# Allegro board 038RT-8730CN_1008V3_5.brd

Outline 645.8 x 470 mm; copper layers: TOP, L02_DGND, L03_SIGNAL, L04_DGND, L05_SIGNAL, L06_DGND, L07_SIGNAL, L08_DGND, L09_SIGNAL, L10_DGND, L11_SIGNAL, L12_DGND, L13_DPS, L14_DGND, L15_DPS, L16_DGND, L17_DPS, L18_DGND, L19_DPS, L20_DGND, L21_DPS, L22_DGND, L23_USER_CBIT, L24_DPS, L25_DGND, L26_SIGNAL, L27_DGND, L28_SIGNAL, L29_DGND, L30_SIGNAL, L31_DGND, L32_SIGNAL, L33_DGND, L34_SIGNAL, L35_DGND, BOTTOM. Coordinates in mm from the lower left corner of the outline.
Outline path: 0,465 0,323.39 0,322.6 arc(1.46,319.06) 5,317.6 50.8,317.6 50.8,152.4 5,152.4 arc(1.47,150.94) 0,147.4 0,5.79 0,5 arc(1.46,1.46) 5,0 640.8,0 arc(644.34,1.46) 645.8,5 645.8,465 arc(644.34,468.54) 640.8,470 5,470 arc(1.46,468.54) 0,465

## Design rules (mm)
net group DIFFPAIR0: nets S0_HSDM S0_HSDP
net group DIFFPAIR2: nets S0_PB5 S0_PB6
net group DIFFPAIR3: nets S0_1_AOUT_RN S0_1_AOUT_RP
net group DIFFPAIR4: nets S0_PA20 S0_PA21
net group DIFFPAIR5: nets S0_2_AOUT_RN S0_2_AOUT_RP
net group DIFFPAIR6: nets S0_PA22 S0_PA23
net group DIFFPAIR7: nets S0_PB5_AOUT_RP_2 S0_PB6_AOUT_RN_2
net group DIFFPAIR8: nets S0_PB3 S0_PB4
net group DIFFPAIR9: nets S0_1_AOUT_LN S0_1_AOUT_LP
net group DIFFPAIR10: nets S0_2_AOUT_LN S0_2_AOUT_LP
net group DIFFPAIR11: nets S0_PB3_AOUT_LP_2 S0_PB4_AOUT_LN_2
net group DIFFPAIR12: nets S0_PA24 S0_PA25
net group DIFFPAIR13: nets S0_PA28 S0_PA29
net group DIFFPAIR14: nets S0_MIPITX_DATAN_0 S0_MIPITX_DATAP_0
net group DIFFPAIR15: nets S0_MIPITX_CKN S0_MIPITX_CKP
net group DIFFPAIR16: nets S0_MIPITX_DATAN_1 S0_MIPITX_DATAP_1
net group DIFFPAIR17: nets S1_HSDM S1_HSDP
net group DIFFPAIR19: nets S1_MIPITX_CKN S1_MIPITX_CKP
net group DIFFPAIR20: nets S1_MIPITX_DATAN_0 S1_MIPITX_DATAP_0
net group DIFFPAIR21: nets S1_MIPITX_DATAN_1 S1_MIPITX_DATAP_1
net group DIFFPAIR22: nets S1_PB3_AOUT_LP_2 S1_PB4_AOUT_LN_2
net group DIFFPAIR23: nets S1_PB5_AOUT_RP_2 S1_PB6_AOUT_RN_2
net group DIFFPAIR24: nets S1_PA22 S1_PA23
net group DIFFPAIR25: nets S1_PA28 S1_PA29
net group DIFFPAIR26: nets S1_2_AOUT_LN S1_2_AOUT_LP
net group DIFFPAIR27: nets S1_2_AOUT_RN S1_2_AOUT_RP
net group DIFFPAIR28: nets S1_PA20 S1_PA21
net group DIFFPAIR29: nets S1_PA24 S1_PA25
net group DIFFPAIR30: nets S1_1_AOUT_LN S1_1_AOUT_LP
net group DIFFPAIR31: nets S1_1_AOUT_RN S1_1_AOUT_RP
net group DIFFPAIR32: nets S1_PB5 S1_PB6
net group DIFFPAIR33: nets S1_PB3 S1_PB4
net group DIFFPAIR35: nets S2_HSDM S2_HSDP
net group DIFFPAIR36: nets S3_MIPITX_CKN S3_MIPITX_CKP
net group DIFFPAIR37: nets S3_MIPITX_DATAN_0 S3_MIPITX_DATAP_0
net group DIFFPAIR38: nets S3_MIPITX_DATAN_1 S3_MIPITX_DATAP_1
net group DIFFPAIR39: nets S3_PB5_AOUT_RP_2 S3_PB6_AOUT_RN_2
net group DIFFPAIR40: nets S3_PA22 S3_PA23
net group DIFFPAIR41: nets S3_PB3_AOUT_LP_2 S3_PB4_AOUT_LN_2
net group DIFFPAIR42: nets S3_PA28 S3_PA29
net group DIFFPAIR43: nets S3_2_AOUT_LN S3_2_AOUT_LP
net group DIFFPAIR44: nets S3_PA24 S3_PA25
net group DIFFPAIR45: nets S3_2_AOUT_RN S3_2_AOUT_RP
net group DIFFPAIR46: nets S3_PA20 S3_PA21
net group DIFFPAIR47: nets S3_1_AOUT_LN S3_1_AOUT_LP
net group DIFFPAIR48: nets S3_PB3 S3_PB4
net group DIFFPAIR49: nets S3_1_AOUT_RN S3_1_AOUT_RP
net group DIFFPAIR50: nets S3_PB5 S3_PB6
net group DIFFPAIR52: nets S3_HSDM S3_HSDP
net group DIFFPAIR53: nets S2_MIPITX_CKN S2_MIPITX_CKP
net group DIFFPAIR54: nets S2_MIPITX_DATAN_0 S2_MIPITX_DATAP_0
net group DIFFPAIR55: nets S2_MIPITX_DATAN_1 S2_MIPITX_DATAP_1
net group DIFFPAIR56: nets S2_PB3_AOUT_LP_2 S2_PB4_AOUT_LN_2
net group DIFFPAIR57: nets S2_PA28 S2_PA29
net group DIFFPAIR58: nets S2_PB5_AOUT_RP_2 S2_PB6_AOUT_RN_2
net group DIFFPAIR59: nets S2_PA22 S2_PA23
net group DIFFPAIR60: nets S2_2_AOUT_LN S2_2_AOUT_LP
net group DIFFPAIR61: nets S2_2_AOUT_RN S2_2_AOUT_RP
net group DIFFPAIR62: nets S2_PA20 S2_PA21
net group DIFFPAIR63: nets S2_PA24 S2_PA25
net group DIFFPAIR64: nets S2_1_AOUT_LN S2_1_AOUT_LP
net group DIFFPAIR65: nets S2_PB3 S2_PB4
net group DIFFPAIR66: nets S2_1_AOUT_RN S2_1_AOUT_RP
net group DIFFPAIR67: nets S2_PB5 S2_PB6
net group DIFFPAIR69: nets S7_HSDM S7_HSDP
net group DIFFPAIR70: nets S7_MIPITX_CKN S7_MIPITX_CKP
net group DIFFPAIR71: nets S7_MIPITX_DATAN_0 S7_MIPITX_DATAP_0
net group DIFFPAIR72: nets S7_MIPITX_DATAN_1 S7_MIPITX_DATAP_1
net group DIFFPAIR73: nets S7_PB3_AOUT_LP_2 S7_PB4_AOUT_LN_2
net group DIFFPAIR74: nets S7_PA28 S7_PA29
net group DIFFPAIR75: nets S7_PB5_AOUT_RP_2 S7_PB6_AOUT_RN_2
net group DIFFPAIR76: nets S7_PA22 S7_PA23
net group DIFFPAIR77: nets S7_2_AOUT_LN S7_2_AOUT_LP
net group DIFFPAIR78: nets S7_2_AOUT_RN S7_2_AOUT_RP
net group DIFFPAIR79: nets S7_PA24 S7_PA25
net group DIFFPAIR80: nets S7_PA20 S7_PA21
net group DIFFPAIR81: nets S7_1_AOUT_LN S7_1_AOUT_LP
net group DIFFPAIR82: nets S7_PB3 S7_PB4
net group DIFFPAIR83: nets S7_1_AOUT_RN S7_1_AOUT_RP
net group DIFFPAIR84: nets S7_PB5 S7_PB6
net group DIFFPAIR86: nets S6_HSDM S6_HSDP
net group DIFFPAIR87: nets S6_MIPITX_CKN S6_MIPITX_CKP
net group DIFFPAIR88: nets S6_MIPITX_DATAN_0 S6_MIPITX_DATAP_0
net group DIFFPAIR89: nets S6_MIPITX_DATAN_1 S6_MIPITX_DATAP_1
net group DIFFPAIR90: nets S6_PB3_AOUT_LP_2 S6_PB4_AOUT_LN_2
net group DIFFPAIR91: nets S6_PA28 S6_PA29
net group DIFFPAIR92: nets S6_PB5_AOUT_RP_2 S6_PB6_AOUT_RN_2
net group DIFFPAIR93: nets S6_PA22 S6_PA23
net group DIFFPAIR94: nets S6_2_AOUT_LN S6_2_AOUT_LP
net group DIFFPAIR95: nets S6_PA24 S6_PA25
net group DIFFPAIR96: nets S6_2_AOUT_RN S6_2_AOUT_RP
net group DIFFPAIR97: nets S6_PA20 S6_PA21
net group DIFFPAIR98: nets S6_1_AOUT_LN S6_1_AOUT_LP
net group DIFFPAIR99: nets S6_PB3 S6_PB4
net group DIFFPAIR100: nets S6_1_AOUT_RN S6_1_AOUT_RP
net group DIFFPAIR101: nets S6_PB5 S6_PB6
net group DIFFPAIR103: nets S5_HSDM S5_HSDP
net group DIFFPAIR104: nets S5_MIPITX_CKN S5_MIPITX_CKP
net group DIFFPAIR105: nets S5_MIPITX_DATAN_0 S5_MIPITX_DATAP_0
net group DIFFPAIR106: nets S5_MIPITX_DATAN_1 S5_MIPITX_DATAP_1
net group DIFFPAIR107: nets S5_PB5_AOUT_RP_2 S5_PB6_AOUT_RN_2
net group DIFFPAIR108: nets S5_PA22 S5_PA23
net group DIFFPAIR109: nets S5_PB3_AOUT_LP_2 S5_PB4_AOUT_LN_2
net group DIFFPAIR110: nets S5_PA28 S5_PA29
net group DIFFPAIR111: nets S5_2_AOUT_LN S5_2_AOUT_LP
net group DIFFPAIR112: nets S5_PA24 S5_PA25
net group DIFFPAIR113: nets S5_2_AOUT_RN S5_2_AOUT_RP
net group DIFFPAIR114: nets S5_PA20 S5_PA21
net group DIFFPAIR115: nets S5_1_AOUT_RN S5_1_AOUT_RP
net group DIFFPAIR116: nets S5_1_AOUT_LN S5_1_AOUT_LP
net group DIFFPAIR117: nets S5_PB3 S5_PB4
net group DIFFPAIR118: nets S5_PB5 S5_PB6
net group DIFFPAIR120: nets S4_HSDM S4_HSDP
net group DIFFPAIR121: nets S4_MIPITX_CKN S4_MIPITX_CKP
net group DIFFPAIR122: nets S4_MIPITX_DATAN_0 S4_MIPITX_DATAP_0
net group DIFFPAIR123: nets S4_MIPITX_DATAN_1 S4_MIPITX_DATAP_1
net group DIFFPAIR124: nets S4_PB5_AOUT_RP_2 S4_PB6_AOUT_RN_2
net group DIFFPAIR125: nets S4_PA22 S4_PA23
net group DIFFPAIR126: nets S4_PB3_AOUT_LP_2 S4_PB4_AOUT_LN_2
net group DIFFPAIR127: nets S4_PA28 S4_PA29
net group DIFFPAIR128: nets S4_2_AOUT_RN S4_2_AOUT_RP
net group DIFFPAIR129: nets S4_PA20 S4_PA21
net group DIFFPAIR130: nets S4_2_AOUT_LN S4_2_AOUT_LP
net group DIFFPAIR131: nets S4_PA24 S4_PA25
net group DIFFPAIR132: nets S4_1_AOUT_RN S4_1_AOUT_RP
net group DIFFPAIR133: nets S4_PB5 S4_PB6
net group DIFFPAIR134: nets S4_1_AOUT_LN S4_1_AOUT_LP
net group DIFFPAIR135: nets S4_PB3 S4_PB4
net group S0_PB23_24: nets S0_PB23 S0_PB24
net group S0_PB23_PB24_SIC: nets S0_PB23_SICK S0_PB24_SIDD
net group S0_PB25_26: nets S0_PB25 S0_PB26
net group S0_PB25_PB26_I2C: nets S0_PB25_I2C_SCL S0_PB26_I2C_SDA
net group S1_PB23_24: nets S1_PB23 S1_PB24
net group S1_PB25_26: nets S1_PB25 S1_PB26
net group S2_PB23_24: nets S2_PB23 S2_PB24
net group S2_PB25_26: nets S2_PB25 S2_PB26
net group S3_PB23_24: nets S3_PB23 S3_PB24
net group S3_PB25_26: nets S3_PB25 S3_PB26
net group S4_PB23_24: nets S4_PB23 S4_PB24
net group S4_PB25_26: nets S4_PB25 S4_PB26
net group S4_XIO: nets S4_XI S4_XO
net group S5_PB23_24: nets S5_PB23 S5_PB24
net group S5_PB25_26: nets S5_PB25 S5_PB26
net group S6_PB23_24: nets S6_PB23 S6_PB24
net group S6_PB25_26: nets S6_PB25 S6_PB26
net group S7_PB23_24: nets S7_PB23 S7_PB24
net group S7_PB25_26: nets S7_PB25 S7_PB26
net group S0_FLASH: nets S0_SPI_CLK/PB28 S0_SPI_CS/PC0 S0_SPI_D0/PB29 S0_SPI_D1/PB31 S0_SPI_D2/PB30 S0_SPI_D3/PB27
net group S1_FLASH: nets S1_SPI_CLK/PB28 S1_SPI_CS/PC0 S1_SPI_D0/PB29 S1_SPI_D1/PB31 S1_SPI_D2/PB30 S1_SPI_D3/PB27
net group S2_FLASH: nets S2_SPI_CLK/PB28 S2_SPI_CS/PC0 S2_SPI_D0/PB29 S2_SPI_D1/PB31 S2_SPI_D2/PB30 S2_SPI_D3/PB27
net group S3_FLASH: nets S3_SPI_CLK/PB28 S3_SPI_CS/PC0 S3_SPI_D0/PB29 S3_SPI_D1/PB31 S3_SPI_D2/PB30 S3_SPI_D3/PB27
net group S4_FLASH: nets S4_SPI_CLK/PB28 S4_SPI_CS/PC0 S4_SPI_D0/PB29 S4_SPI_D1/PB31 S4_SPI_D2/PB30 S4_SPI_D3/PB27
net group S5_FLASH: nets S5_SPI_CLK/PB28 S5_SPI_CS/PC0 S5_SPI_D0/PB29 S5_SPI_D1/PB31 S5_SPI_D2/PB30 S5_SPI_D3/PB27
net group S6_FLASH: nets S6_SPI_CLK/PB28 S6_SPI_CS/PC0 S6_SPI_D0/PB29 S6_SPI_D1/PB31 S6_SPI_D2/PB30 S6_SPI_D3/PB27
net group S7_FLASH: nets S7_SPI_CLK/PB28 S7_SPI_CS/PC0 S7_SPI_D0/PB29 S7_SPI_D1/PB31 S7_SPI_D2/PB30 S7_SPI_D3/PB27

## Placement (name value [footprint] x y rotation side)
ATX_VD0V9  HDR-8X2-M  [CONN_8X2_2P54MM_PH]  508.46 101.18 90 top
ATX_VD1V8  HDR-8X2-M  [CONN_8X2_2P54MM_PH]  372.08 101.18 90 top
ATX_VD33  HDR-8X2-M  [CONN_8X2_2P54MM_PH]  243.83 101.18 90 top
BD1  BD120-1.5A-S4-MU  [FB0402]  281.19 215.24 270 bottom
BD2  BD120-1.5A-S4-MU  [FB0402]  296.96 212.38 180 bottom
BD3  BD120-1.5A-S4-MU  [FB0402]  280.15 215.24 270 bottom
BD5  BD120-1.5A-S4-MU  [FB0402]  277.33 205.67 0 bottom
BD7  BD120-1.5A-S4-MU  [FB0402]  282.24 215.24 270 bottom
BD9  BD120-1.5A-S4-MU  [FB0402]  301.2 202.45 180 bottom
BD11  BD120-1.5A-S4-MU  [FB0402]  296.96 211.34 180 bottom
BD12  BD120-1.5A-S4-MU  [FB0402]  289.07 215.24 270 bottom
BD13  BD120-1.5A-S4-MU  [FB0402]  277.36 198.82 0 bottom
BD15  BD120-1.5A-S4-MU  [FB0402]  280.48 195.03 0 bottom
BD16  BD120-1.5A-S4-MU  [FB0402]  283.8 201.66 180 bottom
BD17  BD120-1.5A-S4-MU  [FB0402]  283.8 200.62 180 bottom
BD18  BD120-1.5A-S4-MU  [FB0402]  295.71 197.57 180 bottom
BD19  BD120-1.5A-S4-MU  [FB0402]  295.71 196.37 180 bottom
BD20  BD120-1.5A-S4-MU  [FB0402]  275.79 205.62 270 bottom
BD21  BD120-1.5A-S4-MU  [FB0402]  295.71 194.23 180 bottom
BD22  BD120-1.5A-S4-MU  [FB0402]  282.3 191.38 180 bottom
BD23  BD120-1.5A-S4-MU  [FB0402]  282.3 193.44 0 bottom
BD27  NC/BD120-1.5A-S4-MU  [FB0402]  223.73 189.87 180 bottom
BD28  BD120-1.5A-S4-MU  [FB0402]  276.81 208.45 270 bottom
BD29  BD120-1.5A-S4-MU  [FB0402]  286.81 215.24 270 bottom
BD30  BD120-1.5A-S4-MU  [FB0402]  276.96 211.26 225 bottom
BD31  BD120-1.5A-S4-MU  [FB0402]  293.85 214.77 180 bottom
BD32  BD120-1.5A-S4-MU  [FB0402]  246.28 190.29 270 top
BD33  BD120-1.5A-S4-MU  [FB0402]  279.76 86.03 270 bottom
BD34  BD120-1.5A-S4-MU  [FB0402]  283.48 189.65 0 bottom
BD35  BD120-1.5A-S4-MU  [FB0402]  293.63 194.23 180 bottom
BD36  BD120-1.5A-S4-MU  [FB0402]  275.32 198.83 0 bottom
BD37  BD120-1.5A-S4-MU  [FB0402]  291.21 215.24 270 bottom
BD42  NC/BD120-3A-S8  [FB0805]  262.04 73.1 270 bottom
BD43  NC/BD120-3A-S8  [FB0805]  389.42 72.95 270 bottom
BD44  NC/BD120-3A-S8  [FB0805]  319.37 69.9 270 bottom
BD48  NC/BD120-3A-S8  [FB0805]  350.33 70 90 bottom
BD50  NC/BD120-3A-S8  [FB0805]  376.8 125.15 0 bottom
BD51  NC/BD120-3A-S8  [FB0805]  376.8 132.1 0 bottom
BD52  NC/BD120-3A-S8  [FB0805]  376.8 138.84 0 bottom
BD56  NC/BD120-3A-S8  [FB0805]  376.8 146.76 0 bottom
BD57  NC/BD120-3A-S8  [FB0805]  157.57 70.66 270 bottom
BD58  NC/BD120-3A-S8  [FB0805]  167.73 70.66 270 bottom
BD59  NC/BD120-3A-S8  [FB0805]  536.87 70.66 270 bottom
BD60  NC/BD120-3A-S8  [FB0805]  547.03 70.66 270 bottom
BD61  NC/BD120-3A-S8  [FB0805]  165.07 394.16 90 bottom
BD62  NC/BD120-3A-S8  [FB0805]  154.91 394.16 90 bottom
BD63  NC/BD120-3A-S8  [FB0805]  546.78 394.16 90 bottom
BD64  NC/BD120-3A-S8  [FB0805]  536.62 394.16 90 bottom
BD65  NC/BD120-3A-S8  [FB0805]  402.73 394.16 90 bottom
BD66  NC/BD120-3A-S8  [FB0805]  392.57 394.16 90 bottom
BD67  NC/BD120-3A-S8  [FB0805]  382.41 394.16 90 bottom
BD68  NC/BD120-3A-S8  [FB0805]  372.25 394.16 90 bottom
BD69  NC/BD120-3A-S8  [FB0805]  298.01 146.56 180 bottom
BD70  NC/BD120-3A-S8  [FB0805]  298.01 139.6 180 bottom
BD71  NC/BD120-3A-S8  [FB0805]  298.01 132.87 180 bottom
BD72  NC/BD120-3A-S8  [FB0805]  298.01 124.94 180 bottom
BDB74  BD100-3A-SA  [FB1206]  28.8 363.86 0 bottom
BDB75  BD100-3A-SA  [FB1206]  28.8 367.04 0 bottom
BDB76  BD100-3A-SA  [FB1206]  28.8 382.91 0 bottom
BDB77  BD100-3A-SA  [FB1206]  28.8 386.09 0 bottom
BDB80  BD100-3A-SA  [FB1206]  205.1 103.08 270 bottom
BDB81  BD100-3A-SA  [FB1206]  234.94 85.94 0 bottom
BDB82  BD100-3A-SA  [FB1206]  333.34 103.08 270 bottom
BDB83  BD100-3A-SA  [FB1206]  363.19 85.94 0 bottom
BDB86  BD100-3A-SA  [FB1206]  469.73 103.08 270 bottom
BDB87  BD100-3A-SA  [FB1206]  499.57 85.94 0 bottom
C1  NC/1P-25-N-S2-WA  [C0201]  289.16 196.56 45 top
C2  10P-50-N-S2-MU  [C0201]  293.49 191.58 300 top
C3  NC/1.2P-50-N-S2-MU  [C0201]  290.97 195.6 45 top
C4  NC/1P-25-N-S2-WA  [C0201]  287.81 196.25 225 top
C5  NC/1.2P-50-N-S2-MU  [C0201]  288.77 194.43 225 top
C6  10P-50-N-S2-MU  [C0201]  290.67 190.77 90 top
C7  NC/10P-50-N-S2-MU  [C0201]  290.37 190.47 180 top
C8  CNC-S2  [C0201]  290.37 185.6 180 top
C9  NC/1P-25-N-S2-WA  [C0201]  286.87 195.72 180 bottom
C10  NC/1.2P-50-N-S2-MU  [C0201]  286.27 193.75 180 bottom
C11  NC/1P-25-N-S2-WA  [C0201]  285.1 196.37 180 top
C12  NC/1.2P-50-N-S2-MU  [C0201]  284.5 194.4 180 top
C13  10P-50-N-S2-MU  [C0201]  284.8 186.76 90 top
C14  NC/10P-50-N-S2-MU  [C0201]  285.1 186.46 0 top
C15  CNC-S2  [C0201]  285.1 184.64 0 top
C16  NC/1P-25-N-S2-WA  [C0201]  285.1 196.37 180 bottom
C17  NC/0.1U-35-X-S2-MU  [C0201]  293.63 200.2 180 bottom
C18  NC/0.1U-35-X-S2-MU  [C0201]  293.63 199.35 180 bottom
C19  NC/1.2P-50-N-S2-MU  [C0201]  284.5 194.4 180 bottom
C20  0.1U-35-X-S2-MU  [C0201]  293.63 197.12 0 bottom
C21  0.1U-35-X-S2-MU  [C0201]  293.63 197.97 0 bottom
C22  0.1U-16-X-S4-MU  [C0402]  243.74 190.26 90 top
C23  0.9P-50-N-S4-MU  [C0402]  276.6 203.41 270 top
C24  0.1U-25-X-S4-TY  [C0402]  223.76 190.95 0 bottom
C25  0.9P-50-N-S4-MU  [C0402]  276.6 200.64 90 top
C38  1P-50-N-S4-WA  [C0402]  215.74 182.57 0 bottom
C39  22P-50-N-S4-AVX  [C0402]  212.34 182.57 0 bottom
C40  1P-50-N-S4-WA  [C0402]  215.74 189.84 0 bottom
C41  22P-50-N-S4-AVX  [C0402]  212.34 189.84 0 bottom
C44  0.1U-35-X-S2-MU  [C0201]  283.93 205.5 0 bottom
C45  0.1U-35-X-S2-MU  [C0201]  292.41 209.41 270 bottom
C46  0.1U-35-X-S2-MU  [C0201]  283.93 204.65 0 bottom
C47  0.1U-35-X-S2-MU  [C0201]  292.63 202.19 180 bottom
C48  0.1U-35-X-S2-MU  [C0201]  279.77 202.74 180 top
C49  0.1U-35-X-S2-MU  [C0201]  292.63 205.91 180 bottom
C52  0.1U-35-X-S2-MU  [C0201]  283.93 206.35 0 bottom
C53  10U-10-X-S4-SS  [C0402]  267.75 206.49 90 bottom
C54  0.1U-35-X-S2-MU  [C0201]  288.82 209.41 270 bottom
C55  0.1U-25-X-S4-TY  [C0402]  270.03 206.49 90 bottom
C56  0.1U-35-X-S2-MU  [C0201]  296.74 203.42 0 top
C57  NC/10U-10-X-S4-SS  [C0402]  268.88 206.49 90 bottom
C58  0.1U-35-X-S2-MU  [C0201]  283.66 213.94 90 top
C59  0.1U-35-X-S2-MU  [C0201]  292.63 207.4 180 bottom
C60  10U-10-X-S4-SS  [C0402]  299.1 212.43 0 bottom
C61  0.1U-35-X-S2-MU  [C0201]  287.88 209.4 270 bottom
C62  22U-25-X-S8-MU  [C0805]  267.63 214.73 0 bottom
C63  22U-25-X-S8-MU  [C0805]  267.63 216.76 0 bottom
C64  0.1U-35-X-S2-MU  [C0201]  279.77 200.61 180 top
C65  47U-16-T-SC  [CODE_C]  241.16 196.21 180 bottom
C66  10U-16-T-SA  [CODE_A]  241.19 196.21 180 top
C67  10U-10-X-S4-SS  [C0402]  299.1 211.31 0 bottom
C68  22U-10-T-SA  [CODE_A]  298.49 169.02 0 bottom
C69  22U-10-T-SA  [CODE_A]  298.49 171.61 0 bottom
C70  22U-10-T-SA  [CODE_A]  298.49 174.18 0 bottom
C71  22U-10-T-SA  [CODE_A]  298.49 171.61 0 top
C72  22U-10-T-SA  [CODE_A]  298.49 169.02 0 top
C73  10U-10-X-S4-SS  [C0402]  275.28 197.76 180 bottom
C74  0.1U-35-X-S2-MU  [C0201]  286.58 200.79 90 bottom
C75  0.1U-35-X-S2-MU  [C0201]  296.74 200.67 0 top
C76  10U-10-X-S4-SS  [C0402]  280.45 196.1 180 bottom
C77  0.1U-35-X-S2-MU  [C0201]  285.76 200.79 90 bottom
C78  0.1U-35-X-S2-MU  [C0201]  279.77 201.29 180 top
C79  0.1U-35-X-S2-MU  [C0201]  279.77 199.92 180 top
C83  10U-10-X-S4-SS  [C0402]  295.74 198.66 0 bottom
C84  0.1U-35-X-S2-MU  [C0201]  288.09 200.79 90 bottom
C85  0.1U-35-X-S2-MU  [C0201]  287.36 200.79 90 bottom
C88  0.1U-35-X-S2-MU  [C0201]  279.77 203.4 180 top
C89  10U-10-X-S4-SS  [C0402]  274.26 206.99 180 bottom
C90  10U-10-X-S4-SS  [C0402]  295.74 195.29 0 bottom
C91  0.1U-35-X-S2-MU  [C0201]  287.68 198.01 0 bottom
C92  22U-25-X-S8-MU  [C0805]  310.5 171.07 180 bottom
C93  22U-25-X-S8-MU  [C0805]  310.5 171.07 180 top
C94  47U-16-T-SC  [CODE_C]  310.43 167.76 180 bottom
C95  10U-16-T-SA  [CODE_A]  310.43 167.76 180 top
C96  10U-10-X-S4-SS  [C0402]  297.82 198.66 0 bottom
C97  10U-10-X-S4-SS  [C0402]  281.83 190.88 270 top
C98  0.1U-35-X-S2-MU  [C0201]  280.89 191.78 270 top
C99  10U-10-X-S4-SS  [C0402]  282.77 192.94 270 top
C100  0.1U-35-X-S2-MU  [C0201]  283.05 196.09 270 top
C101  10U-10-X-S4-SS  [C0402]  274.26 205.15 180 bottom
C102  0.1U-35-X-S2-MU  [C0201]  292.63 203.7 180 bottom
C105  0.1U-35-X-S2-MU  [C0201]  292.63 204.49 180 bottom
C106  10U-10-X-S4-SS  [C0402]  297.65 225.88 90 bottom
C107  0.1U-35-X-S2-MU  [C0201]  296.74 204.79 0 top
C108  0.1U-25-X-S4-TY  [C0402]  296.53 225.88 90 bottom
C109  NC/10U-10-X-S4-SS  [C0402]  298.77 225.88 90 bottom
C110  1U-10-X-S4-MU  [C0402]  298.36 200.67 180 top
C111  10U-10-X-S4-SS  [C0402]  276.81 207.48 270 top
C112  0.1U-35-X-S2-MU  [C0201]  278.83 208.2 270 top
C113  10U-25-X-S6-MU  [C0603]  302.96 205.99 90 bottom
C116  22U-25-X-S8-MU  [C0805]  288.03 218.11 180 bottom
C117  22U-25-X-S8-MU  [C0805]  288.02 220.27 180 bottom
C118  10U-10-X-S4-SS  [C0402]  285.72 215.27 90 bottom
C119  0.1U-35-X-S2-MU  [C0201]  286.94 209.4 270 bottom
C120  47U-16-T-SC  [CODE_C]  256.02 167.31 0 bottom
C121  10U-16-T-SA  [CODE_A]  256.02 167.31 0 top
C122  10U-10-X-S4-SS  [C0402]  297.82 197.55 0 bottom
C123  10U-10-X-S4-SS  [C0402]  276.28 211.28 135 top
C124  0.1U-35-X-S2-MU  [C0201]  279.77 210.08 180 top
C125  10U-10-X-S4-SS  [C0402]  293.38 215.27 90 top
C126  0.1U-35-X-S2-MU  [C0201]  293.33 213.89 180 top
C127  10U-10-X-S4-SS  [C0402]  245.01 190.26 90 top
C128  0.1U-35-X-S2-MU  [C0201]  242.47 190.26 90 top
C129  10U-10-X-S4-SS  [C0402]  273.26 198.82 180 bottom
C130  0.1U-25-X-S4-TY  [C0402]  278.67 86.06 90 bottom
C131  22U-10-T-SA  [CODE_A]  284.21 88.62 0 bottom
C132  22U-10-T-SA  [CODE_A]  284.21 83.49 0 top
C133  22U-10-T-SA  [CODE_A]  284.21 86.06 0 top
C134  22U-10-T-SA  [CODE_A]  284.21 86.06 0 bottom
C135  22U-10-T-SA  [CODE_A]  284.21 83.49 0 bottom
C136  10U-10-X-S4-SS  [C0402]  287.84 225.88 90 bottom
C137  0.1U-25-X-S4-TY  [C0402]  286.72 225.88 90 bottom
C138  NC/10U-10-X-S4-SS  [C0402]  288.95 225.88 90 bottom
C139  22U-25-X-S8-MU  [C0805]  276.49 225.56 270 bottom
C140  47U-16-T-SC  [CODE_C]  262.63 169.21 270 bottom
C141  10U-16-T-SA  [CODE_A]  262.63 169.21 270 top
C142  22U-25-X-S8-MU  [C0805]  278.79 225.56 270 bottom
C143  NC/10P-50-N-S4-WA  [C0402]  297 208.8 180 bottom
C144  NC/10P-50-N-S4-WA  [C0402]  297 207.63 180 bottom
C145  NC/10P-50-N-S4-WA  [C0402]  187.11 175.2 90 top
C146  NC/10P-50-N-S4-WA  [C0402]  187.11 178.4 90 top
C147  NC/10P-50-N-S4-WA  [C0402]  187.11 167.93 90 top
C148  NC/10P-50-N-S4-WA  [C0402]  187.11 171.13 90 top
C149  NC/10P-50-N-S4-WA  [C0402]  187.11 183.83 90 top
C150  NC/10P-50-N-S4-WA  [C0402]  187.11 187.03 90 top
C152  0.1U-35-X-S2-MU  [C0201]  289.67 209.41 270 bottom
C153  CNC-S2  [C0201]  292.12 205.24 180 bottom
C524  0.1U-50-X7R-S4-YA  [C0402]  337.53 146.28 180 bottom
C525  0.1U-50-X7R-S4-YA  [C0402]  368.01 146.28 180 bottom
C528  0.1U-50-X7R-S4-YA  [C0402]  352.77 146.28 180 bottom
C539  0.1U-50-X7R-S4-YA  [C0402]  322.29 146.28 180 bottom
C540  10U-10-X-S6-MU  [C0603]  366.11 142.47 180 bottom
C541  10U-10-X-S6-MU  [C0603]  366.11 127.23 180 bottom
C542  10U-10-X-S6-MU  [C0603]  350.87 142.47 180 bottom
C543  10U-10-X-S6-MU  [C0603]  350.87 127.23 180 bottom
C544  10U-10-X-S6-MU  [C0603]  335.63 142.47 180 bottom
C545  10U-10-X-S6-MU  [C0603]  335.63 127.23 180 bottom
C546  10U-10-X-S6-MU  [C0603]  320.39 142.47 180 bottom
C547  10U-10-X-S6-MU  [C0603]  320.39 127.23 180 bottom
C548  0.1U-50-X7R-S4-YA  [C0402]  368.01 131.04 180 bottom
C549  0.1U-50-X7R-S4-YA  [C0402]  352.77 131.04 180 bottom
C550  0.1U-50-X7R-S4-YA  [C0402]  322.29 131.04 180 bottom
C551  0.1U-50-X7R-S4-YA  [C0402]  337.53 131.04 180 bottom
C552  0.1U-50-X7R-S4-YA  [C0402]  322.29 115.8 180 bottom
C553  0.1U-50-X7R-S4-YA  [C0402]  337.53 115.8 180 bottom
C554  0.1U-50-X7R-S4-YA  [C0402]  368.01 115.8 180 bottom
C555  0.1U-50-X7R-S4-YA  [C0402]  352.77 115.8 180 bottom
CB631  220U-10-T-SD  [CODE_D]  30.71 351.8 0 bottom
CB632  220U-10-T-SD  [CODE_D]  30.71 344.18 0 bottom
CB633  10U-10-T-SA-AVX  [CODE_A]  28.17 339.1 0 bottom
CB634  0.1U-16-X5R-S2-WA  [C0201]  21.8 339.1 180 bottom
CB635  220U-10-T-SD  [CODE_D]  18.01 378.47 180 bottom
CB636  10U-10-T-SA-AVX  [CODE_A]  25.88 376.31 270 bottom
CB637  0.1U-16-X5R-S2-WA  [C0201]  28.17 381.01 0 bottom
CB638  0.1U-16-X5R-S2-WA  [C0201]  29.44 361.32 0 bottom
CB639  10U-35-T-SC  [CODE_C]  30.71 358.15 0 bottom
CB640  47U-25-T-SD-AVX  [CODE_D]  18.01 358.15 180 bottom
CB641  0.1U-16-X5R-S2-WA  [C0201]  35.79 391.8 0 bottom
CB642  10U-10-T-SA-AVX  [CODE_A]  36.42 389.26 0 bottom
CB643  220U-10-T-SD  [CODE_D]  37.69 384.18 0 bottom
CB647  0.1U-16-X5R-S2-WA  [C0201]  34.2 374.02 0 bottom
CB648  10U-35-T-SC  [CODE_C]  36.42 370.85 0 bottom
CB649  47U-25-T-SD-AVX  [CODE_D]  37.69 365.13 0 bottom
CB650  0.1U-16-X5R-S2-WA  [C0201]  209.69 87.9 0 bottom
CB651  3300P-50-X7R-S4-HS  [C0402]  212.72 87.21 180 bottom
CB652  CNC-S4  [C0402]  213.35 85.3 270 bottom
CB653  0.1U-16-X5R-S2-WA  [C0201]  211.45 97.37 270 bottom
CB654  220U-10-T-SD  [CODE_D]  205.1 94.19 270 bottom
CB655  10U-10-X-S4-SS  [C0402]  210.18 97.37 90 bottom
CB656  100P-50-N-S4-YA  [C0402]  205.73 106.26 90 bottom
CB657  0.1U-16-X5R-S2-WA  [C0201]  204.46 106.26 270 bottom
CB658  0.1U-16-X5R-S2-WA  [C0201]  212.08 99.27 0 bottom
CB659  NC/100P-50-N-S4-MU  [C0402]  215.89 93.56 270 bottom
CB660  CNC-S4  [C0402]  216.53 89.11 180 bottom
CB661  220U-10-T-SD  [CODE_D]  231.77 94.19 90 bottom
CB662  0.1U-16-X-S4-MU  [C0402]  226.69 85.3 270 bottom
CB663  10U-10-X-S4-SS  [C0402]  228.59 85.3 270 bottom
CB664  220U-10-T-SD  [CODE_D]  237.48 94.19 90 bottom
CB665  0.1U-16-X5R-S2-WA  [C0201]  337.93 87.9 0 bottom
CB666  3300P-50-X7R-S4-HS  [C0402]  340.96 87.21 180 bottom
CB667  CNC-S4  [C0402]  341.6 85.3 270 bottom
CB668  0.1U-16-X5R-S2-WA  [C0201]  339.69 97.37 270 bottom
CB669  220U-10-T-SD  [CODE_D]  333.34 94.19 270 bottom
CB670  10U-10-X-S4-SS  [C0402]  338.42 97.37 90 bottom
CB671  100P-50-N-S4-YA  [C0402]  333.98 106.26 90 bottom
CB672  0.1U-16-X5R-S2-WA  [C0201]  332.71 106.26 270 bottom
CB673  0.1U-16-X5R-S2-WA  [C0201]  340.33 99.27 0 bottom
CB674  NC/100P-50-N-S4-MU  [C0402]  344.14 93.56 270 bottom
CB675  CNC-S4  [C0402]  344.77 89.11 180 bottom
CB676  220U-10-T-SD  [CODE_D]  360.01 94.19 90 bottom
CB677  0.1U-16-X-S4-MU  [C0402]  354.93 85.3 270 bottom
CB678  10U-10-X-S4-SS  [C0402]  356.84 85.3 270 bottom
CB679  220U-10-T-SD  [CODE_D]  365.73 94.19 90 bottom
CB695  0.1U-16-X5R-S2-WA  [C0201]  474.32 87.9 0 bottom
CB696  3300P-50-X7R-S4-HS  [C0402]  477.35 87.21 180 bottom
CB697  CNC-S4  [C0402]  477.98 85.3 270 bottom
CB698  0.1U-16-X5R-S2-WA  [C0201]  476.08 97.37 270 bottom
CB699  220U-10-T-SD  [CODE_D]  469.73 94.19 270 bottom
CB700  10U-10-X-S4-SS  [C0402]  474.81 97.37 90 bottom
CB701  100P-50-N-S4-YA  [C0402]  470.36 106.26 90 bottom
CB702  0.1U-16-X5R-S2-WA  [C0201]  469.09 106.26 270 bottom
CB703  0.1U-16-X5R-S2-WA  [C0201]  476.71 99.27 0 bottom
CB704  NC/100P-50-N-S4-MU  [C0402]  480.52 93.56 270 bottom
CB705  CNC-S4  [C0402]  481.16 89.11 180 bottom
CB706  220U-10-T-SD  [CODE_D]  496.4 94.19 90 bottom
CB707  0.1U-16-X-S4-MU  [C0402]  491.32 85.3 270 bottom
CB708  10U-10-X-S4-SS  [C0402]  493.22 85.3 270 bottom
CB709  220U-10-T-SD  [CODE_D]  502.11 94.19 90 bottom
CT1  680P-50-X7R-S4-HS  [C0402]  292.36 75.28 90 bottom
CT2  10U-25-X7R-SA  [C1206]  323.61 73.07 180 bottom
CT3  4.7U-25-X7R-S8-TY  [C0805]  323.61 69.17 180 bottom
CT4  10U-25-X7R-SA  [C1206]  344.89 73.07 0 bottom
CT5  4.7U-25-X7R-S8-TY  [C0805]  344.89 70.46 0 bottom
CT6  10U-25-X7R-SA  [C1206]  274.34 69.87 180 bottom
CT7  4.7U-25-X7R-S8-TY  [C0805]  274.34 73.23 180 bottom
CT8  10U-50-X-SB-MU  [C1210]  334.94 69.49 0 bottom
CT9  4.7U-50-X-S8-MU  [C0805]  334.94 73.46 0 bottom
CT10  10U-50-X-SB-MU  [C1210]  355.26 69.49 180 bottom
CT11  4.7U-50-X-S8-MU  [C0805]  355.26 73.46 180 bottom
CT12  10U-50-X-SB-MU  [C1210]  365.35 69.49 180 bottom
CT13  4.7U-50-X-S8-MU  [C0805]  365.35 73.46 180 bottom
CT14  0.1U-16-X-S4-MU-1  [C0402]  373.01 74.26 180 bottom
CT15  680P-50-N-S8  [C0805]  294 75.73 90 bottom
CT16  0.1U-25-X-S6  [C0603]  305.19 76.15 180 bottom
CT17  22U-10-T-SA  [CODE_A]  304.59 73.33 180 bottom
CT18  22U-10-T-SA  [CODE_A]  304.59 70.28 180 bottom
CT19  22U-10-T-SA  [CODE_A]  313.93 76.38 0 bottom
CT20  22U-10-T-SA  [CODE_A]  313.93 70.28 0 bottom
CT21  22U-10-T-SA  [CODE_A]  313.93 73.33 0 bottom
D1  RCLAMP3321P-SLP1006P2  [DIODE_1X0P6MM]  293.73 190.31 30 top
D2  RCLAMP3321P-SLP1006P2  [DIODE_1X0P6MM]  290.24 186.49 0 top
D3  RCLAMP3321P-SLP1006P2  [DIODE_1X0P6MM]  285.23 185.52 180 top
FD1  -  [FD_040_V2]  151.87 165.82 0 top
FD2  -  [FD_040_V2]  549.81 165.82 0 top
FD3  -  [FD_040_V2]  549.81 308.06 0 top
FD4  -  [FD_040_V2]  151.87 308.06 0 top
FD5  -  [FD_040_V2]  549.81 165.82 180 bottom
FD6  -  [FD_040_V2]  549.81 308.06 180 bottom
FD7  -  [FD_040_V2]  151.87 308.06 180 bottom
FD8  -  [FD_040_V2]  151.87 165.82 180 bottom
FD9  -  [FD_040_V2]  141.71 74.38 0 top
FD10  -  [FD_040_V2]  549.81 79.46 0 top
FD11  -  [FD_040_V2]  549.81 389.34 0 top
FD12  -  [FD_040_V2]  151.87 389.34 0 top
FD13  -  [FD_040_V2]  141.71 74.38 180 bottom
FD14  -  [FD_040_V2]  549.81 79.46 180 bottom
FD15  -  [FD_040_V2]  549.81 389.34 180 bottom
FD16  -  [FD_040_V2]  151.87 389.34 180 bottom
FUSEB1  MF-R185-40A-D  [FUSE_12X9P2MM]  23.09 347.99 270 bottom
FUSEB2  MF-R185-40A-D  [FUSE_12X9P2MM]  23.09 388.63 270 bottom
FUSEB3  MF-R185-40A-D  [FUSE_12X9P2MM]  23.09 368.31 270 bottom
H1  M3-HOLE  [M3_NPTH169]  126.47 236.94 0 top
H2  M3-HOLE  [M3_NPTH169]  397.41 74.38 0 top
H3  M3-HOLE  [M3_NPTH169]  356.77 394.42 0 top
H4  M3-HOLE  [M3_NPTH169]  570.13 236.94 0 top
HOLE_CABLE3  DEBUGHOLE-15X15MM  [SLOT_NPTH_SQ15X15MM]  136.63 379.18 0 top
HOLE_CABLE4  DEBUGHOLE-15X15MM  [SLOT_NPTH_SQ15X15MM]  565.05 79.46 0 top
J1  HDR-4X1-F-1  [CONN_4X1_2P54MM_FL10P5MM]  194.53 191.57 270 top
J2  HDR-4X1-F-1  [CONN_4X1_2P54MM_FL10P5MM]  273.27 83.52 270 top
J3  HDR-4X1-F-1  [CONN_4X1_2P54MM_FL10P5MM]  188.31 191.57 270 top
J4  HDR-8X1-M  [JP_8P_100]  267.69 141.44 270 top
J5  HDR-1X1-M  [JP_1P_RD070_040]  288.19 91.4 90 top
J6  HDR-2X1-M  [JP_2P_100]  285.28 91.4 90 top
J7  HDR-2X1-M  [JP_2P_100]  412.92 115.4 0 top
J8  HDR-2X1-M  [JP_2P_100]  416.73 115.4 0 top
J9  HDR-2X1-M  [JP_2P_100]  409.11 115.4 0 top
JB1  ATX-10X2-MR  [CONN_PWR10X2_4P2MM_ML]  19.57 434.19 90 bottom
K1  CU/UA2-12NJ-A-V2  [RL_NECUA2_12V_V2]  253.33 186.76 0 bottom
K2  CU/UA2-12NJ-A-V2  [RL_NECUA2_12V_V2]  253.33 179.75 0 bottom
K3  CU/UA2-12NJ-A-V2  [RL_NECUA2_12V_V2]  253.33 172.74 0 bottom
K4  CU/UA2-12NJ-A-V2  [RL_NECUA2_12V_V2]  204.41 194.61 0 bottom
K5  CU/RF303-12-A-V2_EX  [RL_RF303_12V_V2]  305.5 228.94 270 bottom
K6  CU/UA2-12NJ-A-V2  [RL_NECUA2_12V_V2]  281.99 99.22 90 bottom
K7  CU/RF303-12-A-V2_EX  [RL_RF303_12V_V2]  253.64 194.99 270 bottom
K8  CU/UA2-12NJ-A-V2  [RL_NECUA2_12V_V2]  204.41 186.21 0 bottom
K9  CU/UA2-12NJ-A-V2  [RL_NECUA2_12V_V2]  309.74 181.5 180 bottom
K10  CU/UA2-12NJ-A-V2  [RL_NECUA2_12V_V2]  230.24 177.57 0 bottom
K11  CU/UA2-12NJ-A-V2  [RL_NECUA2_12V_V2]  204.41 170.31 0 bottom
K12  CU/UA2-12NJ-A-V2  [RL_NECUA2_12V_V2]  215.84 177.57 0 bottom
K13  CU/UA2-12NJ-A-V2  [RL_NECUA2_12V_V2]  204.41 177.57 0 bottom
K14  CU/UA2-12NJ-A-V2  [RL_NECUA2_12V_V2]  230.24 170.31 0 bottom
K15  CU/UA2-12NJ-A-V2  [RL_NECUA2_12V_V2]  215.84 170.31 0 bottom
K16  CU/UA2-12NJ-A-V2  [RL_NECUA2_12V_V2]  227.27 194.61 0 bottom
K18  CU/UA2-12NJ-A-V2  [RL_NECUA2_12V_V2]  227.27 186.21 0 bottom
K19  CU/UA2-12NJ-A-V2  [RL_NECUA2_12V_V2]  215.84 186.21 0 bottom
K20  CU/UA2-12NJ-A-V2  [RL_NECUA2_12V_V2]  283.15 222.11 90 bottom
K21  CU/UA2-12NJ-A-V2  [RL_NECUA2_12V_V2]  270.68 210.58 0 bottom
K22  CU/UA2-12NJ-A-V2  [RL_NECUA2_12V_V2]  267.58 200.09 90 bottom
K23  CU/UA2-12NJ-A-V2  [RL_NECUA2_12V_V2]  291.3 173.15 90 bottom
K25  CU/UA2-12NJ-A-V2  [RL_NECUA2_12V_V2]  281.15 230.56 0 bottom
K26  CU/UA2-12NJ-A-V2  [RL_NECUA2_12V_V2]  309.74 175.14 180 bottom
K28  CU/UA2-12NJ-A-V2  [RL_NECUA2_12V_V2]  294.18 230.49 0 bottom
K29  CU/UA2-12NJ-A-V2  [RL_NECUA2_12V_V2]  292.97 222.11 90 bottom
K30  CU/UA2-12NJ-A-V2  [RL_NECUA2_12V_V2]  183.63 194.81 270 bottom
K31  CU/UA2-12NJ-A-V2  [RL_NECUA2_12V_V2]  183.63 183.38 270 bottom
K32  CU/UA2-12NJ-A-V2  [RL_NECUA2_12V_V2]  183.63 171.95 270 bottom
K33  CU/UA2-12NJ-A-V2  [RL_NECUA2_12V_V2]  324.95 173.14 90 bottom
K34  CU/UA2-12NJ-A-V2  [RL_NECUA2_12V_V2]  192.98 177.57 0 bottom
K35  CU/UA2-12NJ-A-V2  [RL_NECUA2_12V_V2]  192.98 170.31 0 bottom
K36  CU/UA2-12NJ-A-V2  [RL_NECUA2_12V_V2]  192.98 186.21 0 bottom
K37  CU/UA2-12NJ-A-V2  [RL_NECUA2_12V_V2]  215.84 194.61 0 bottom
K38  CU/UA2-12NJ-A-V2  [RL_NECUA2_12V_V2]  318.61 173.14 90 bottom
K39  CU/UA2-12NJ-A-V2  [RL_NECUA2_12V_V2]  275.02 99.22 90 bottom
KT1  CU/UA2-12NJ-A-V2  [RL_NECUA2_12V_V2]  285.64 73.18 180 bottom
L1  L2.2U-1.15A-S2.0X1.6-TDK  [IND_VL252012E]  271.97 206.04 270 bottom
L3  L2.2U-1.15A-S2.0X1.6-TDK  [IND_VL252012E]  297.28 223.34 90 bottom
L4  L2.2U-1.15A-S2.0X1.6-TDK  [IND_VL252012E]  287.47 223.34 90 bottom
LB1  L10U-3.8A-S10.2X10-GO  [IND_GSSR2104]  222.88 93.56 270 bottom
LB2  L10U-3.8A-S10.2X10-GO  [IND_GSSR2104]  351.12 93.56 270 bottom
LB4  L10U-3.8A-S10.2X10-GO  [IND_GSSR2104]  487.51 93.56 270 bottom
LDB1  LDG-2-S8  [LED_0805]  322.66 76.38 0 top
LDB2  LDG-2-S8  [LED_0805]  345.84 76.38 180 top
LDB3  LDG-2-S8  [LED_0805]  273.39 76.35 0 top
LDB4  LDG-2-S8  [LED_0805]  335.89 76.38 180 top
LDB5  LDG-2-S8  [LED_0805]  354.31 76.38 0 top
LDB6  LDG-2-S8  [LED_0805]  366.3 76.38 180 top
LDB19  LDR-2-S8  [LED_0805]  230.5 83.4 90 top
LDB20  LDR-2-S8  [LED_0805]  358.74 83.4 90 top
LDB22  LDR-2-S8  [LED_0805]  495.13 83.4 90 top
LOGO1  LOGO_RT_Realtek  [LOGO_RT_REALTEK]  318.13 425.98 0 top
LOGO2  -  [LOGO_KT_KSMT]  438.09 135 0 top
LRB1  330-1-S6  [R0603]  324.46 76.38 180 bottom
LRB2  330-1-S6  [R0603]  344.04 76.38 0 bottom
LRB3  1K-1-S6  [R0603]  275.19 76.35 0 bottom
LRB4  2K-1-S6  [R0603]  334.09 76.38 180 bottom
LRB5  1.5K-1-S6  [R0603]  356.11 76.38 0 bottom
LRB6  1.5K-1-S6  [R0603]  364.5 76.38 180 bottom
NOREF  -  []  277 281.45 90 top
NOREF#2  -  []  295.29 184.5 0 top
NOREF#3  -  []  287.82 209.36 90 top
NOREF#4  -  []  240.78 219.8 0 top
NOREF#5  -  []  309.34 243.1 0 top
NOREF#6  -  []  214.04 237.29 0 top
NOREF#7  -  []  294.22 257.01 90 top
NOREF#8  -  []  219.44 193.01 90 top
NOREF#9  -  []  315.93 207.58 90 top
NOREF#10  -  []  412.85 167.49 90 top
NOREF#11  -  []  462.76 225.45 0 top
NOREF#12  -  []  500.02 191.16 0 top
NOREF#13  -  []  209.66 260.19 90 top
NOREF#14  -  []  395.48 254.44 90 top
NOREF#15  -  []  293.47 192.26 0 top
NOREF#16  -  []  211.45 89.67 0 top
NOREF#17  -  []  453.01 261.2 0 top
NOREF#18  -  []  323.66 273.64 90 top
NOREF#19  -  []  326.13 185.02 0 top
NOREF#20  -  []  411.07 196.08 90 top
NOREF#21  -  []  408.28 257.05 90 top
NOREF#22  -  []  182.03 276.62 90 top
NOREF#23  -  []  507.47 154.21 90 top
NOREF#24  -  []  258.58 211.04 90 top
NOREF#25  -  []  502.07 270.82 90 top
NOREF#26  -  []  330.76 195.38 0 top
NOREF#27  -  []  265.03 207.58 0 top
NOREF#28  -  []  331.82 373.84 90 top
NOREF#29  -  []  521.42 224.92 0 top
NOREF#30  -  []  402.5 80.68 90 top
NOREF#31  -  []  170.58 201.84 0 top
NOREF#32  -  []  407 247.55 90 top
NOREF#33  -  []  268.11 294.51 0 top
NOREF#34  -  []  508.74 177.92 90 top
NOREF#35  -  []  374.57 218.11 90 top
NOREF#36  -  []  323.07 83.49 0 top
NOREF#37  -  []  396.16 202.17 90 top
NOREF#38  -  []  408.95 256.35 0 top
NOREF#39  -  []  209.66 251.79 90 top
NOREF#40  -  []  466.61 361.76 90 top
NOREF#41  -  []  333.47 192.26 0 top
NOREF#42  -  []  155.68 196.61 0 top
NOREF#43  -  []  318.83 207.9 90 top
NOREF#44  -  []  507.47 222.79 90 top
NOREF#45  -  []  286.94 209.1 90 top
NOREF#46  -  []  505.67 211.37 90 top
NOREF#47  -  []  369.35 210.01 0 top
NOREF#48  -  []  309.3 246 90 top
NOREF#49  -  []  485.88 272.39 90 top
NOREF#50  -  []  363.63 264.65 0 top
NOREF#51  -  []  296.84 174.18 0 top
NOREF#52  -  []  516.65 271.03 0 top
NOREF#53  -  []  430.8 45.5 0 top
NOREF#54  -  []  401.7 269.33 0 top
NOREF#55  -  []  501.06 377.26 90 top
NOREF#56  -  []  461.95 379.82 90 top
NOREF#57  -  []  380.3 213 0 top
NOREF#58  -  []  289.86 196.29 0 top
NOREF#59  -  []  292.33 204.49 0 top
NOREF#60  -  []  360.8 200 0 top
NOREF#61  -  []  353.33 261.92 0 top
NOREF#62  -  []  293.23 266.23 0 top
NOREF#63  -  []  468.16 191.16 0 top
NOREF#64  -  []  368.1 259.55 90 top
NOREF#65  -  []  453.01 226.91 0 top
NOREF#66  -  []  289.71 255.72 90 top
NOREF#67  -  []  294.43 264.17 90 top
NOREF#68  -  []  211.84 218.9 0 top
NOREF#69  -  []  418.02 348.24 0 top
NOREF#70  -  []  373.34 251.84 0 top
NOREF#71  -  []  491.79 174.12 0 top
NOREF#72  -  []  517.92 273.39 0 top
NOREF#73  -  []  290.55 269.37 90 top
NOREF#74  -  []  412.19 252 90 top
NOREF#75  -  []  372.33 203.7 0 top
NOREF#76  -  []  274.08 260.75 90 top
NOREF#77  -  []  284.8 246.46 0 top
NOREF#78  -  []  376.14 200.99 0 top
NOREF#79  -  []  371.14 185.99 90 top
NOREF#80  -  []  225.75 378.52 90 top
NOREF#81  -  []  50.8 465 0 top
NOREF#82  -  []  395.93 207.58 90 top
NOREF#83  -  []  215.43 364.96 90 top
NOREF#84  -  []  289.34 246.99 0 top
NOREF#85  -  []  488.59 213.62 90 top
NOREF#86  -  []  251.53 219.45 0 top
NOREF#87  -  []  296.44 200.67 0 top
NOREF#88  -  []  419.2 167.5 90 top
NOREF#89  -  []  482.56 259.74 0 top
NOREF#90  -  []  465.96 267 0 top
NOREF#91  -  []  391.3 248 90 top
NOREF#92  -  []  446.29 172.14 90 top
NOREF#93  -  []  458.44 206.81 90 top
NOREF#94  -  []  190.11 258.1 90 top
NOREF#95  -  []  381.98 300.55 0 top
NOREF#96  -  []  188.92 122.77 90 top
NOREF#97  -  []  322.41 251.74 90 top
NOREF#98  -  []  409.71 255.72 90 top
NOREF#99  -  []  222.39 367.16 90 top
NOREF#100  -  []  296.44 203.42 0 top
NOREF#101  -  []  282.41 191.74 90 top
NOREF#102  -  []  289.71 195.72 90 top
NOREF#103  -  []  368.66 251.82 0 top
NOREF#104  -  []  371.82 265.24 0 top
NOREF#105  -  []  517.92 170.52 0 top
NOREF#106  -  []  288.76 269.36 90 top
NOREF#107  -  []  399.47 201.29 0 top
NOREF#108  -  []  334.33 152.43 0 top
NOREF#109  -  []  455.27 377.23 0 top
NOREF#110  -  []  315.32 300.88 90 top
NOREF#111  -  []  408.28 197.05 90 top
NOREF#112  -  []  404.5 186.78 0 top
NOREF#113  -  []  286.62 210 0 top
NOREF#114  -  []  301.41 170.34 90 top
NOREF#115  -  []  182.03 285.84 90 top
NOREF#116  -  []  429 298.4 0 top
NOREF#117  -  []  461.2 344.43 90 top
NOREF#118  -  []  275.48 194.44 90 top
NOREF#119  -  []  359.63 383.9 90 top
NOREF#120  -  []  397.01 176.74 0 top
NOREF#121  -  []  50.8 465 0 top
NOREF#122  -  []  365.98 187.8 0 top
NOREF#123  -  []  168.6 117.24 0 top
NOREF#124  -  []  367.47 256.04 0 top
NOREF#125  -  []  372.9 169.15 90 top
NOREF#126  -  []  391.73 301.95 90 top
NOREF#127  -  []  251.53 288.03 0 top
NOREF#128  -  []  373.34 191.84 0 top
NOREF#129  -  []  321.96 364.96 90 top
NOREF#130  -  []  273.4 300.87 0 top
NOREF#131  -  []  352.28 201.89 0 top
NOREF#132  -  []  332.33 205.91 0 top
NOREF#133  -  []  296.84 169.02 0 top
NOREF#134  -  []  445.07 230.28 0 top
NOREF#135  -  []  309.34 176.74 0 top
NOREF#136  -  []  465.73 205.21 90 top
NOREF#137  -  []  261.92 228.95 0 top
NOREF#138  -  []  459.51 165.21 90 top
NOREF#139  -  []  291.14 245.99 90 top
NOREF#140  -  []  493.99 198.42 0 top
NOREF#141  -  []  276.62 99.62 90 top
NOREF#142  -  []  34.77 389.26 0 top
NOREF#143  -  []  514.57 184.16 90 top
NOREF#144  -  []  182.03 171.54 90 top
NOREF#145  -  []  187.11 258.63 0 top
NOREF#146  -  []  365.7 256.05 0 top
NOREF#147  -  []  360.89 251.48 90 top
NOREF#148  -  []  477.74 295.43 0 top
NOREF#149  -  []  383.97 167.76 0 top
NOREF#150  -  []  297.43 210.27 90 top
NOREF#151  -  []  280.39 102.82 0 top
NOREF#152  -  []  414.42 204.17 90 top
NOREF#153  -  []  435.67 295.86 90 top
NOREF#154  -  []  404.81 83.52 90 top
NOREF#155  -  []  505.42 216.81 0 top
NOREF#156  -  []  414.42 207.08 90 top
NOREF#157  -  []  402.3 269.2 0 top
NOREF#158  -  []  232.16 232.1 0 top
NOREF#159  -  []  477.16 276.99 0 top
NOREF#160  -  []  214.04 253.19 0 top
NOREF#161  -  []  284.5 244.96 0 top
NOREF#162  -  []  290.32 255.4 0 top
NOREF#163  -  []  326.3 253.44 90 top
NOREF#164  -  []  317.29 116.51 90 top
NOREF#165  -  []  376.84 169.02 0 top
NOREF#166  -  []  394.28 268.98 90 top
NOREF#167  -  []  477.74 183.92 0 top
NOREF#168  -  []  322.3 256.5 0 top
NOREF#169  -  []  52.77 405.06 0 top
NOREF#170  -  []  286.57 194.43 90 top
NOREF#171  -  []  350.3 293.92 90 top
NOREF#172  -  []  516.65 287.84 90 top
NOREF#173  -  []  55.8 0 90 top
NOREF#174  -  []  366.08 200.19 0 top
NOREF#175  -  []  288.67 255.4 90 top
NOREF#176  -  []  416.44 203.42 0 top
NOREF#177  -  []  435.61 188.21 90 top
NOREF#178  -  []  374.58 295.32 90 top
NOREF#179  -  []  196.58 287.48 90 top
NOREF#180  -  []  182.03 185.18 90 top
NOREF#181  -  []  228.44 175.97 0 top
NOREF#182  -  []  366.76 121.95 0 top
NOREF#183  -  []  321.55 228.96 0 top
NOREF#184  -  []  292.55 335.47 90 top
NOREF#185  -  []  279.47 203.4 0 top
NOREF#186  -  []  359.35 228.96 0 top
NOREF#187  -  []  406.08 260.19 0 top
NOREF#188  -  []  410.07 192.35 0 top
NOREF#189  -  []  508.74 228.11 90 top
NOREF#190  -  []  369.87 196.73 0 top
NOREF#191  -  []  366.9 187.37 90 top
NOREF#192  -  []  368.95 256.35 0 top
NOREF#193  -  []  258.58 272.61 90 top
NOREF#194  -  []  243.59 277.38 90 top
NOREF#195  -  []  364.8 255.09 90 top
NOREF#196  -  []  333.29 120.26 90 top
NOREF#197  -  []  191.18 237.29 0 top
NOREF#198  -  []  477.16 298.09 90 top
NOREF#199  -  []  367.82 269.36 90 top
NOREF#200  -  []  375.42 199.03 90 top
NOREF#201  -  []  503.87 257.08 0 top
NOREF#202  -  []  324.8 247.74 90 top
NOREF#203  -  []  393.3 240 90 top
NOREF#204  -  []  446.56 95.22 90 top
NOREF#205  -  []  214.37 228.19 0 top
NOREF#206  -  []  323.07 88.62 0 top
NOREF#207  -  []  365.7 184.32 90 top
NOREF#208  -  []  364.53 205.39 90 top
NOREF#209  -  []  170.58 236.13 0 top
NOREF#210  -  []  55.8 0 90 top
NOREF#211  -  []  446.56 99.62 90 top
NOREF#212  -  []  32.67 390.53 0 top
NOREF#213  -  []  266.77 83.12 90 top
NOREF#214  -  []  321.57 258.96 90 top
NOREF#215  -  []  450.39 84.76 0 top
NOREF#216  -  []  288.5 270.01 0 top
NOREF#217  -  []  368.3 265 0 top
NOREF#218  -  []  400.35 268.16 90 top
NOREF#219  -  []  216.24 203 0 top
NOREF#220  -  []  281.57 209.12 90 top
NOREF#221  -  []  325.3 267 90 top
NOREF#222  -  []  175.18 228.15 90 top
NOREF#223  -  []  410.3 203 90 top
NOREF#224  -  []  516.65 230.69 90 top
NOREF#225  -  []  505.42 198.42 0 top
NOREF#226  -  []  407.28 259.55 90 top
NOREF#227  -  []  290.9 262.85 90 top
NOREF#228  -  []  409.42 254.63 0 top
NOREF#229  -  []  211.84 287.48 0 top
NOREF#230  -  []  351.08 208.98 0 top
NOREF#231  -  []  222.39 361.76 90 top
NOREF#232  -  []  194.53 191.57 90 top
NOREF#233  -  []  514.57 193.38 90 top
NOREF#234  -  []  514.57 229.88 90 top
NOREF#235  -  []  404.8 185.52 0 top
NOREF#236  -  []  284.8 268.5 0 top
NOREF#237  -  []  388.65 295.32 90 top
NOREF#238  -  []  321.57 259.65 90 top
NOREF#239  -  []  445.07 223.27 0 top
NOREF#240  -  []  329.7 269.37 90 top
NOREF#241  -  []  477.16 294.03 0 top
NOREF#242  -  []  287.13 87.35 90 top
NOREF#243  -  []  363.63 265.5 0 top
NOREF#244  -  []  401.39 129.12 90 top
NOREF#245  -  []  366.3 194.08 90 top
NOREF#246  -  []  198.76 208.86 0 top
NOREF#247  -  []  373.47 192.26 0 top
NOREF#248  -  []  528.44 333.27 0 top
NOREF#249  -  []  50.8 5 0 top
NOREF#250  -  []  275.6 217.7 0 top
NOREF#251  -  []  367.28 199.55 90 top
NOREF#252  -  []  235.49 174.57 90 top
NOREF#253  -  []  327.68 260.19 0 top
NOREF#254  -  []  450.39 262.8 90 top
NOREF#255  -  []  179.95 268.22 0 top
NOREF#256  -  []  480.36 251.1 0 top
NOREF#257  -  []  288.41 260.19 0 top
NOREF#258  -  []  325.7 267.17 0 top
NOREF#259  -  []  253.73 171.14 0 top
NOREF#260  -  []  342.96 75.38 90 top
NOREF#261  -  []  213.15 381.09 0 top
NOREF#262  -  []  418.02 348.24 90 top
NOREF#263  -  []  415.13 272.93 90 top
NOREF#264  -  []  294.58 295.32 90 top
NOREF#265  -  []  468.77 106.86 0 top
NOREF#266  -  []  511.37 198.78 0 top
NOREF#267  -  []  478.56 238.79 90 top
NOREF#268  -  []  182.03 214.07 0 top
NOREF#269  -  []  475.37 359.7 90 top
NOREF#270  -  []  244.06 396.4 0 top
NOREF#271  -  []  355.1 262.13 90 top
NOREF#272  -  []  284.8 208.5 0 top
NOREF#273  -  []  404.57 256.05 90 top
NOREF#274  -  []  458.33 272.52 90 top
NOREF#275  -  []  333.32 260.2 0 top
NOREF#276  -  []  286.37 296.27 90 top
NOREF#277  -  []  364.8 185.52 0 top
NOREF#278  -  []  57.77 1.56 90 top
NOREF#279  -  []  292.33 202.19 0 top
NOREF#280  -  []  404.8 196.37 0 top
NOREF#281  -  []  263.3 190 90 top
NOREF#282  -  []  452.5 83.49 0 top
NOREF#283  -  []  489.17 302.69 0 top
NOREF#284  -  []  348.65 295.32 90 top
NOREF#285  -  []  505.92 211.02 0 top
NOREF#286  -  []  213.49 228.19 0 top
NOREF#287  -  []  373.03 273.89 0 top
NOREF#288  -  []  200.41 203 0 top
NOREF#289  -  []  182.03 230.9 90 top
NOREF#290  -  []  355.5 287.55 0 top
NOREF#291  -  []  371.37 285.71 0 top
NOREF#292  -  []  484.5 239.12 90 top
NOREF#293  -  []  334.33 137.19 0 top
NOREF#294  -  []  374.22 257.01 90 top
NOREF#295  -  []  514.57 250.53 90 top
NOREF#296  -  []  182.03 294.08 90 top
NOREF#297  -  []  495.85 84.5 90 top
NOREF#298  -  []  428.82 293.25 0 top
NOREF#299  -  []  407 187.55 90 top
NOREF#300  -  []  373.36 250.09 0 top
NOREF#301  -  []  453.25 279.7 90 top
NOREF#302  -  []  640.8 0 90 top
NOREF#303  -  []  238.62 230.5 0 top
NOREF#304  -  []  361.57 198.96 90 top
NOREF#305  -  []  182.03 173.75 90 top
NOREF#306  -  []  421.41 167.75 90 top
NOREF#307  -  []  370.18 288.89 0 top
NOREF#308  -  []  370.35 250.17 0 top
NOREF#309  -  []  353.3 180 90 top
NOREF#310  -  []  283.13 294.52 0 top
NOREF#311  -  []  223.27 287.48 0 top
NOREF#312  -  []  418.69 293.68 90 top
NOREF#313  -  []  502.07 207.32 90 top
NOREF#314  -  []  402.9 269.33 0 top
NOREF#315  -  []  337.34 203.1 90 top
NOREF#316  -  []  284.57 256.05 90 top
NOREF#317  -  []  360.3 293 0 top
NOREF#318  -  []  324.53 264.54 90 top
NOREF#319  -  []  280.3 237 90 top
NOREF#320  -  []  493.99 208.41 0 top
NOREF#321  -  []  399.35 288.95 0 top
NOREF#322  -  []  213.15 381.09 0 top
NOREF#323  -  []  286.33 255.34 90 top
NOREF#324  -  []  488.59 182.52 0 top
NOREF#325  -  []  214.04 168.71 0 top
NOREF#326  -  []  55.8 0 90 top
NOREF#327  -  []  334.57 282.51 90 top
NOREF#328  -  []  28.8 375.04 90 top
NOREF#329  -  []  439.67 188.98 0 top
NOREF#330  -  []  306.14 176.74 0 top
NOREF#331  -  []  292.68 350.14 0 top
NOREF#332  -  []  331.82 373.84 0 top
NOREF#333  -  []  196.33 292.39 90 top
NOREF#334  -  []  548.8 424.5 90 top
NOREF#335  -  []  459.51 233.79 90 top
NOREF#336  -  []  21.5 339.1 0 top
NOREF#337  -  []  369.34 246.99 0 top
NOREF#338  -  []  394.08 260.75 90 top
NOREF#339  -  []  170.58 190.41 0 top
NOREF#340  -  []  219.44 287.48 90 top
NOREF#341  -  []  372.33 264.49 0 top
NOREF#342  -  []  486.38 242.29 0 top
NOREF#343  -  []  293.47 252.26 0 top
NOREF#344  -  []  438.34 367.29 0 top
NOREF#345  -  []  325.68 185.52 90 top
NOREF#346  -  []  326.87 254.07 0 top
NOREF#347  -  []  324.53 203.69 90 top
NOREF#348  -  []  188.98 168.71 0 top
NOREF#349  -  []  363.63 206.35 0 top
NOREF#350  -  []  359.15 208.8 0 top
NOREF#351  -  []  55.8 0 90 top
NOREF#352  -  []  372.38 288.89 0 top
NOREF#353  -  []  516.65 202.45 0 top
NOREF#354  -  []  406.57 195.72 0 top
NOREF#355  -  []  289.31 191.57 90 top
NOREF#356  -  []  336.84 169.02 0 top
NOREF#357  -  []  359.47 201.29 0 top
NOREF#358  -  []  211.05 379.8 0 top
NOREF#359  -  []  348.53 148.79 90 top
NOREF#360  -  []  363.61 137.35 0 top
NOREF#361  -  []  282.3 269.2 0 top
NOREF#362  -  []  283.66 213.64 90 top
NOREF#363  -  []  444.4 82 90 top
NOREF#364  -  []  327 187.28 90 top
NOREF#365  -  []  326.94 269.1 90 top
NOREF#366  -  []  284.1 259 0 top
NOREF#367  -  []  327.28 259.55 90 top
NOREF#368  -  []  305.03 267.58 0 top
NOREF#369  -  []  491.79 225.45 0 top
NOREF#370  -  []  291.14 185.99 90 top
NOREF#371  -  []  301.41 167.75 90 top
NOREF#372  -  []  493.99 259.74 0 top
NOREF#373  -  []  227.67 193.01 0 top
NOREF#374  -  []  348.88 268.98 0 top
NOREF#375  -  []  284.53 265.39 90 top
NOREF#376  -  []  370.97 245.28 0 top
NOREF#377  -  []  383.25 295.32 0 top
NOREF#378  -  []  328.88 199.55 90 top
NOREF#379  -  []  299.43 227.49 90 top
NOREF#380  -  []  214.04 210.26 0 top
NOREF#381  -  []  30.51 359.75 0 top
NOREF#382  -  []  482.56 198.42 0 top
NOREF#383  -  []  370.62 253.99 90 top
NOREF#384  -  []  521.42 282.07 0 top
NOREF#385  -  []  400.37 202.42 0 top
NOREF#386  -  []  294.43 265.59 90 top
NOREF#387  -  []  405.13 188.64 0 top
NOREF#388  -  []  329.3 251.52 90 top
NOREF#389  -  []  360.3 177 90 top
NOREF#390  -  []  368.53 227.49 0 top
NOREF#391  -  []  326.58 247.42 0 top
NOREF#392  -  []  397.15 228.96 0 top
NOREF#393  -  []  361.57 269.12 90 top
NOREF#394  -  []  302.85 186 45 top
NOREF#395  -  []  328.66 251.82 0 top
NOREF#396  -  []  412.33 203.7 0 top
NOREF#397  -  []  370.07 245.6 0 top
NOREF#398  -  []  294.58 300.72 90 top
NOREF#399  -  []  200.41 287.48 0 top
NOREF#400  -  []  333.23 267.72 0 top
NOREF#401  -  []  411.82 265.24 0 top
NOREF#402  -  []  345.98 263.69 0 top
NOREF#403  -  []  249.33 253.74 0 top
NOREF#404  -  []  414.3 208.85 90 top
NOREF#405  -  []  323.34 213.34 0 top
NOREF#406  -  []  406.8 187.3 90 top
NOREF#407  -  []  266.21 297.69 90 top
NOREF#408  -  []  341.41 170.34 90 top
NOREF#409  -  []  548.8 424.5 90 top
NOREF#410  -  []  414.43 263.38 90 top
NOREF#411  -  []  286.13 245.02 0 top
NOREF#412  -  []  371.05 276.46 90 top
NOREF#413  -  []  312.72 378.53 0 top
NOREF#414  -  []  640.8 0 90 top
NOREF#415  -  []  292.9 169.15 90 top
NOREF#416  -  []  146.75 48.56 0 top
NOREF#417  -  []  363.98 199.6 90 top
NOREF#418  -  []  290.35 190.17 0 top
NOREF#419  -  []  480.36 182.52 0 top
NOREF#420  -  []  286.87 194.07 0 top
NOREF#421  -  []  320.37 262.42 0 top
NOREF#422  -  []  270.2 300.87 0 top
NOREF#423  -  []  302.3 251 90 top
NOREF#424  -  []  271.08 268.98 0 top
NOREF#425  -  []  336.48 142.02 90 top
NOREF#426  -  []  290.07 245.6 0 top
NOREF#427  -  []  317.9 177.54 0 top
NOREF#428  -  []  191.18 218.9 0 top
NOREF#429  -  []  181.48 213.27 90 top
NOREF#430  -  []  210.19 270.18 0 top
NOREF#431  -  []  284.8 208.5 0 top
NOREF#432  -  []  330.62 193.99 90 top
NOREF#433  -  []  319.69 298.81 0 top
NOREF#434  -  []  479.93 240.39 0 top
NOREF#435  -  []  52.77 6.56 0 top
NOREF#436  -  []  410.55 209.37 90 top
NOREF#437  -  []  468.16 198.42 0 top
NOREF#438  -  []  406.9 247.37 90 top
NOREF#439  -  []  391.3 188 90 top
NOREF#440  -  []  389.81 304.05 90 top
NOREF#441  -  []  365.13 188.64 0 top
NOREF#442  -  []  292.33 207.4 0 top
NOREF#443  -  []  325.7 207.17 0 top
NOREF#444  -  []  503.22 232.71 0 top
NOREF#445  -  []  326.57 254.43 90 top
NOREF#446  -  []  407.45 194.68 90 top
NOREF#447  -  []  326.8 187.3 90 top
NOREF#448  -  []  375.13 212.93 90 top
NOREF#449  -  []  404.8 184.64 0 top
NOREF#450  -  []  155.68 208.04 0 top
NOREF#451  -  []  491.79 208.41 0 top
NOREF#452  -  []  329.86 196.29 0 top
NOREF#453  -  []  485.88 238.1 90 top
NOREF#454  -  []  431.54 183.1 0 top
NOREF#455  -  []  52.77 6.56 0 top
NOREF#456  -  []  388.88 208.98 0 top
NOREF#457  -  []  287.88 269.1 90 top
NOREF#458  -  []  253.48 167.31 0 top
NOREF#459  -  []  413.28 269.37 90 top
NOREF#460  -  []  410.62 253.99 90 top
NOREF#461  -  []  232.16 266.39 0 top
NOREF#462  -  []  413.02 256.8 0 top
NOREF#463  -  []  366.87 254.07 0 top
NOREF#464  -  []  364.8 195.09 90 top
NOREF#465  -  []  293.03 273.89 0 top
NOREF#466  -  []  321.8 294.95 0 top
NOREF#467  -  []  364.8 248.34 0 top
NOREF#468  -  []  296.42 199.08 0 top
NOREF#469  -  []  309.18 256.09 90 top
NOREF#470  -  []  295.47 93.18 0 top
NOREF#471  -  []  327.45 254.68 90 top
NOREF#472  -  []  364.5 186.78 0 top
NOREF#473  -  []  329.31 191.29 90 top
NOREF#474  -  []  340.57 97.33 90 top
NOREF#475  -  []  182.03 297.27 90 top
NOREF#476  -  []  502.07 173.03 90 top
NOREF#477  -  []  412.4 209.11 90 top
NOREF#478  -  []  52.77 6.56 0 top
NOREF#479  -  []  370.32 255.4 0 top
NOREF#480  -  []  493.99 301.29 0 top
NOREF#481  -  []  182.03 271.22 0 top
NOREF#482  -  []  328.82 269.11 90 top
NOREF#483  -  []  52.77 68.06 0 top
NOREF#484  -  []  291.88 269.88 0 top
NOREF#485  -  []  240.78 185.51 0 top
NOREF#486  -  []  381.41 170.34 90 top
NOREF#487  -  []  326.37 296.27 90 top
NOREF#488  -  []  258.94 166.04 90 top
NOREF#489  -  []  198.76 286.08 0 top
NOREF#490  -  []  262.58 335.72 90 top
NOREF#491  -  []  453.01 192.62 0 top
NOREF#492  -  []  331.37 225.71 0 top
NOREF#493  -  []  209.99 89.67 90 top
NOREF#494  -  []  211.05 379.8 0 top
NOREF#495  -  []  453.76 239.5 0 top
NOREF#496  -  []  286.3 207.28 0 top
NOREF#497  -  []  289.11 251.32 90 top
NOREF#498  -  []  240.95 257.6 90 top
NOREF#499  -  []  289.67 209.11 90 top
NOREF#500  -  []  284.8 187.74 90 top
NOREF#501  -  []  200.41 237.29 0 top
NOREF#502  -  []  413.92 204.92 90 top
NOREF#503  -  []  221.09 217.5 90 top
NOREF#504  -  []  210.19 251.79 0 top
NOREF#505  -  []  416.44 204.79 0 top
